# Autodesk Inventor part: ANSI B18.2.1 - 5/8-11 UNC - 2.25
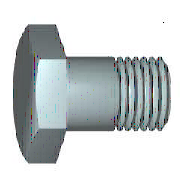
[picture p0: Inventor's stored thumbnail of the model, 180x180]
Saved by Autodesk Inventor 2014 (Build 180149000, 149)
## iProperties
Created: 2008-02
Part Number: ANSI B18.2.1 - 5/8-11 UNC - 2.25
Material: Steel, Mild
Description: Hex Cap Screw
Document SubType Name: Modeling
Standard: ANSI B18.2.1
Designer: floress
Standard Revision: 1996
Standards Organization: ANSI
Language: en-US
Size Designation: 5/8-11 UNC - 2.25
Categories: <MemberInstance><Categories><Category DisplayName="Fasteners" InternalName="e4da775c-781d-43d5-af7c-5136215cf5a6" Mnemonic="FSTN"><Category DisplayName="Bolts"
Density: 7.86 g/cm^3
Mass: 126.207 g
Surface Area: 45.5168 cm^2
Volume: 16.0568 cm^3
Appearance: Steel
IsCustomPart: 0
Author: floress
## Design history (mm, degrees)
sketch "Sketch1"
  geometry: L1 (0, 10.716)-(0, 7.937); L2 (19.05, 7.938)-(57.15, 7.938); L3 (57.15, 7.938)-(57.15, 0); L4 (57.15, 0)-(-0.635, 0); L5 (-12.192, 0)-(68.707, 0) reference; L6 (-0.635, 0)-(-0.635, 10.716); L7 (-0.635, 10.716)-(0, 10.716); L8 (19.05, 7.938)-(13.277, 7.938); L9 (13.277, 7.938)-(0, 7.937); L10 (0, -2.143)-(0, 12.859) reference
  constraints: 16 end point, 2 collinear, 2 perpendicular, 1 parallel
  dimensions: "d0" = 57.15 distance between parallel lines of L3 L1 (= NLG); "d1" = 38.1 distance from line of L2.start L3 (= GEL); "d2" = 15.875 diameter of L2 L4 (= GD); "d9" = 0.6351 distance between parallel lines of L6 L1 (computed from SD); "d10" = 21.43125 diameter of L7 L4 (= SD2); "d13" = 5.77276 distance of L2.start L8.end (computed from GAL); "d14" = 15.875 diameter of L9 L4 (= BDM)
revolve "Body" sketch "Sketch1" stored, may be unused: angle "d12" = 90 deg
sketch "Sketch2"
  geometry: L1 (0, 13.748)-(11.906, 6.874); L2 (11.906, 6.874)-(11.906, -6.874); L3 (11.906, -6.874)-(0, -13.748); L4 (0, -13.748)-(-11.906, -6.874); L5 (-11.906, -6.874)-(-11.906, 6.874); L6 (-11.906, 6.874)-(0, 13.748); 2 further points
  constraints: 12 end point, 1 coincident, 1 vertical, 11 other
  dimensions: "d11" = 23.8125 distance between parallel lines of L5 L2 (= SW)
extrude "Head" join sketch "Sketch2" distance "d3" = 9.28688 (= KOH - SD); taper "d4" = 0 deg
sketch "Sketch4"
  geometry: L1 (-9.922, 11.906)-(-9.922, 13.748); L2 (-9.922, 13.748)-(-8.859, 13.748); L3 (-8.859, 13.748)-(-9.922, 11.906); L4 (-11.779, 0)-(1.222, 0) reference; L5 (-0.635, 13.748)-(-9.922, 13.748) reference; L6 (-9.922, 6.874)-(-9.922, 13.748) reference
  constraints: 6 end point, 2 collinear, 1 perpendicular, 1 vertical
  dimensions: "d5" = 30 deg angle of L3 L1 (= ANG1); "d19" = 23.8125 diameter of L1.start L4 (= SW0)
revolve "Chamfer1" sketch "Sketch4" stored, may be unused: angle "d21" = 90 deg
workplane "Work Plane1"
fillet "Fillet2" dims "d63" = 1.143 (= R)
body "Solid1"
feature "Thread" dims "d15" = 38.1 (= GEL), "d16" = 0
chamfer "Chamfer2" distance "d6" = 1.37414 (= -0.5 x SPD + 0.5 x GD); stored, may be unused: second distance "d7" = 1.37424 (computed from GUL), angle "d55" = 45 deg
other parameters: "NLG" = 57.15 [user parameter; used in 2 equation terms], "GD" = 15.875 (= NND) [user parameter; used in 2 equation terms], "BDM" = 15.875 [user parameter; used in 1 equation term], "KOH" = 9.92188 [user parameter; used in 1 equation term], "GEL" = 38.1 [user parameter; used in 2 equation terms], "SW" = 23.8125 [user parameter; used in 3 equation terms], "SW0" = 23.8125 (= SW) [user parameter; used in 1 equation term], "SPD" = 13.12672 (= GD1) [user parameter; used in 1 equation term], "SD2" = 21.43125 [user parameter; used in 1 equation term], "SD" = 0.635 [user parameter; used in 3 equation terms], "ANG1" = 30 deg [user parameter; used in 1 equation term], "GAL" = 5.77266 [user parameter; used in 1 equation term], "GUL" = 1.37414 [user parameter; used in 2 equation terms], "d8" = 0, "R" = 1.143 [user parameter; used in 1 equation term], "d58" = 0, "d62" = -56.41086 (= -NLG - SD + GUL), "THREADDIA" = 15.875 [user parameter], "TOA" = 30 deg [user parameter], "RR" = 1.524 [user parameter], "PTC" = 2.30909 (computed from TPU) [user parameter], "NND" = 15.875 [user parameter; used in 1 equation term], "E0" = 27.50344 (= 1.155 x SW) [user parameter], "SLG" = 0 [user parameter], "GD1" = 13.12672 [user parameter; used in 1 equation term]
